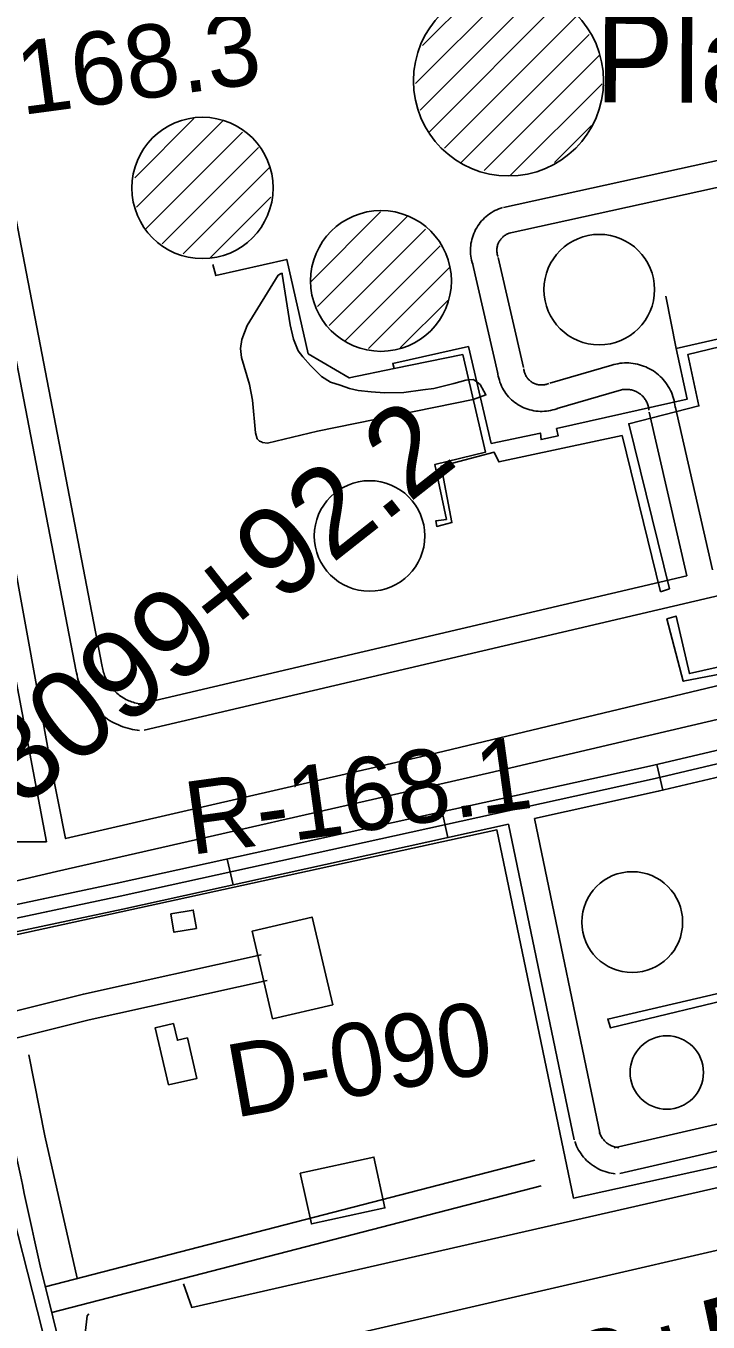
# Model space of a CAD drawing. Extents: x 3392644 to 3430565, y 576657 to 602123.
# Drawn here: x 3414906 to 3415681, y 584566 to 586038 of the extents above; entities that cross this region are included whole.
import ezdxf

# ---------------------------------------------------------------- set-up
doc = ezdxf.new("R2010")
doc.units = 0
for name, color, linetype in [('V-BLDG-IDEN', 7, 'Continuous'), ('V-BLDG-OTLN', 7, 'Continuous'), ('V-DOMW-TANK', 7, 'Continuous'), ('V-RIVR-RANG-IDEN', 7, 'Continuous'), ('V-ROAD-CNTR', 7, 'Continuous'), ('V-SITE-OTLN', 7, 'Continuous'), ('V-SURV-IDEN', 7, 'Continuous'), ('V-TOPO-SHOR', 7, 'Continuous'), ('V-UTIL-LINE', 7, 'Continuous')]:
    doc.layers.add(name, color=color, linetype=linetype)

msp = doc.modelspace()

# ---------------------------------------------------------------- linework, layer by layer
at = {"layer": 'V-BLDG-OTLN'}
for points in [[(3415070.6, 585029.5), (3415096.1, 585033.8), (3415099.6, 585013), (3415074.1, 585008.7)], [(3415186.3, 584910.3), (3415162.9, 585009.8), (3415231.2, 585025.8), (3415254.6, 584926.3)], [(3415067.9, 584835.1), (3415052.8, 584900), (3415073.6, 584904.9), (3415078.1, 584885.9), (3415089.5, 584888.6), (3415100.2, 584842.6)], [(3415217.7, 584735.1), (3415301.3, 584753.3), (3415313.9, 584695.5), (3415230.3, 584677.3)]]:
    msp.add_lwpolyline(points, close=True, dxfattribs=at)
at = {"layer": 'V-DOMW-TANK'}
for p, q in [((3415348.7, 585972.7), (3415458.2, 586082.1)), ((3415353.8, 585942.4), (3415488.3, 586076.9)), ((3415356.5, 586015.8), (3415415.2, 586074.5)), ((3415364.5, 585917.7), (3415511.3, 586064.6)), ((3415381.5, 585899.3), (3415532.2, 586050.1)), ((3415400.2, 585882.7), (3415545.8, 586028.3)), ((3415426.7, 585873.9), (3415557.4, 586004.5)), ((3415456.7, 585868.6), (3415560.7, 585972.5)), ((3415029.6, 585865.7), (3415096.9, 585932.9)), ((3415031.7, 585832.4), (3415129.6, 585930.3)), ((3415041.9, 585807.3), (3415152, 585917.4)), ((3415506.5, 585883), (3415548.5, 585924.9)), ((3415060.8, 585790.8), (3415170.2, 585900.2)), ((3415084.7, 585779.3), (3415182.5, 585877.1)), ((3415115.7, 585775), (3415184.2, 585843.5)), ((3415229.9, 585747.7), (3415309, 585826.9)), ((3415237.1, 585719.6), (3415339.8, 585822.3)), ((3415250.5, 585697.7), (3415360.1, 585807.3)), ((3415268.3, 585680.1), (3415376.5, 585788.3)), ((3415295.4, 585671.9), (3415387.4, 585763.8)), ((3415331.3, 585672.4), (3415385.3, 585726.4))]:
    msp.add_line(p, q, dxfattribs=at)
for centre, radius in [((3415454.3, 585975.7), 108), ((3415106.6, 585854.1), 80.3), ((3415309.4, 585748.5), 80), ((3415557.4, 585738.6), 62.8), ((3415296.4, 585458.8), 62.8), ((3415594.9, 585020.1), 57.3), ((3415634.2, 584849.3), 41.7)]:
    msp.add_circle(centre, radius, dxfattribs=at)
at = {"layer": 'V-ROAD-CNTR'}
for p, q in [((3415622.9, 585199.1), (3415629.8, 585169.9)), ((3415379, 585145.4), (3415385.4, 585116.1)), ((3415134.8, 585091.7), (3415141.3, 585062.4))]:
    msp.add_line(p, q, dxfattribs=at)
for points in [[(3414963.1, 585305), (3414684.5, 586747.9)], [(3414992.6, 585310.6), (3414810.3, 586254.8)], [(3415448.7, 585832.1), (3415983.1, 585949.3)], [(3415455.2, 585802.8), (3415989.5, 585920)], [(3415447.5, 585831.8), (3415445.5, 585831.2), (3415443.3, 585830.3), (3415441, 585829.4), (3415438.9, 585828.4), (3415436.8, 585827.2), (3415434.7, 585826), (3415432.7, 585824.7), (3415430.8, 585823.2), (3415428.9, 585821.7), (3415427.1, 585820.1), (3415425.4, 585818.4), (3415423.8, 585816.7), (3415422.2, 585814.8), (3415420.8, 585812.9), (3415419.4, 585811), (3415418.2, 585808.9), (3415417, 585806.8), (3415415.9, 585804.7), (3415414.9, 585802.5), (3415414.1, 585800.2), (3415413.3, 585798), (3415412.7, 585795.6), (3415412.1, 585793.3), (3415411.7, 585790.9), (3415411.4, 585788.6), (3415411.2, 585786.2), (3415411.1, 585783.8), (3415411.1, 585781.4), (3415411.3, 585779), (3415411.5, 585776.6), (3415411.9, 585774.2), (3415412.4, 585771.9), (3415413, 585769.5), (3415413.6, 585767.4), (3415413.7, 585767.1)], [(3415456.4, 585803.1), (3415455.2, 585802.7), (3415454.2, 585802.4), (3415453.3, 585802), (3415452.5, 585801.6), (3415451.6, 585801.1), (3415450.8, 585800.6), (3415449.9, 585800.1), (3415449.1, 585799.5), (3415448.4, 585798.9), (3415447.7, 585798.2), (3415447, 585797.5), (3415446.3, 585796.8), (3415445.7, 585796.1), (3415445.1, 585795.3), (3415444.5, 585794.5), (3415444, 585793.7), (3415443.5, 585792.8), (3415443.1, 585791.9), (3415442.7, 585791), (3415442.3, 585790.1), (3415442, 585789.2), (3415441.8, 585788.2), (3415441.5, 585787.3), (3415441.4, 585786.3), (3415441.2, 585785.3), (3415441.2, 585784.4), (3415441.1, 585783.4), (3415441.1, 585782.4), (3415441.2, 585781.4), (3415441.3, 585780.5), (3415441.4, 585779.5), (3415441.6, 585778.5), (3415441.9, 585777.6), (3415442.2, 585776.5), (3415442.2, 585776.6)], [(3417410.7, 585793.4), (3415040.3, 585238.2)], [(3415413.3, 585768.5), (3415442.2, 585643.3)], [(3415442.5, 585775.2), (3415471.4, 585650)], [(3415471.7, 585648.7), (3415471.9, 585647.4), (3415472, 585646.4), (3415472.2, 585645.5), (3415472.5, 585644.5), (3415472.8, 585643.6), (3415473.2, 585642.7), (3415473.6, 585641.9), (3415474, 585641), (3415474.5, 585640.1), (3415475, 585639.3), (3415475.5, 585638.5), (3415476.1, 585637.8), (3415476.8, 585637), (3415477.4, 585636.3), (3415478.1, 585635.7), (3415478.8, 585635), (3415479.6, 585634.4), (3415480.4, 585633.8), (3415481.2, 585633.3), (3415482, 585632.8), (3415482.9, 585632.4), (3415483.8, 585632), (3415484.6, 585631.6), (3415485.6, 585631.3), (3415486.5, 585631), (3415487.4, 585630.8), (3415488.4, 585630.6), (3415489.3, 585630.4), (3415490.3, 585630.3), (3415491.2, 585630.3), (3415492.2, 585630.3), (3415493.2, 585630.3), (3415494.1, 585630.4), (3415495.1, 585630.5), (3415496.1, 585630.7), (3415497, 585630.9), (3415497.9, 585631.2), (3415498.9, 585631.5), (3415500, 585631.9)], [(3415501.3, 585632.4), (3415571.8, 585652.9)], [(3415571.8, 585652.9), (3415573.9, 585653.5), (3415576.3, 585654), (3415578.7, 585654.5), (3415581.2, 585654.9), (3415583.6, 585655.1), (3415586.1, 585655.3), (3415588.5, 585655.3), (3415591, 585655.3), (3415593.5, 585655.1), (3415595.9, 585654.8), (3415598.4, 585654.4), (3415600.8, 585653.9), (3415603.2, 585653.3), (3415605.6, 585652.6), (3415607.9, 585651.8), (3415610.2, 585650.8), (3415612.4, 585649.8), (3415614.6, 585648.7), (3415616.8, 585647.5), (3415618.9, 585646.2), (3415620.9, 585644.8), (3415622.9, 585643.3), (3415624.8, 585641.7), (3415626.6, 585640), (3415628.4, 585638.3), (3415630.1, 585636.5), (3415631.7, 585634.6), (3415633.2, 585632.7), (3415634.6, 585630.6), (3415635.9, 585628.6), (3415637.2, 585626.4), (3415638.3, 585624.2), (3415639.4, 585622), (3415640.3, 585619.7), (3415641.1, 585617.4), (3415641.9, 585615), (3415642.5, 585612.6), (3415643, 585610.2), (3415643.5, 585607.8), (3415643.8, 585605.4), (3415643.9, 585604.3)], [(3415441.9, 585644.7), (3415442.2, 585642.6), (3415442.7, 585640.3), (3415443.2, 585638), (3415443.9, 585635.7), (3415444.6, 585633.4), (3415445.5, 585631.2), (3415446.5, 585629), (3415447.5, 585626.8), (3415448.7, 585624.7), (3415450, 585622.7), (3415451.4, 585620.8), (3415452.8, 585618.9), (3415454.4, 585617), (3415456, 585615.3), (3415457.7, 585613.6), (3415459.5, 585612), (3415461.4, 585610.5), (3415463.4, 585609.1), (3415465.4, 585607.8), (3415467.4, 585606.6), (3415469.5, 585605.5), (3415471.7, 585604.5), (3415473.9, 585603.6), (3415476.2, 585602.8), (3415478.5, 585602.1), (3415480.8, 585601.5), (3415483.1, 585601), (3415485.5, 585600.7), (3415487.9, 585600.4), (3415490.3, 585600.3), (3415492.7, 585600.3), (3415495.1, 585600.4), (3415497.5, 585600.6), (3415499.8, 585600.9), (3415502.2, 585601.3), (3415504.5, 585601.9), (3415506.8, 585602.5), (3415509.1, 585603.3), (3415510.9, 585604)], [(3415509.6, 585603.6), (3415580.2, 585624.1)], [(3415580.2, 585624.1), (3415581.6, 585624.5), (3415582.7, 585624.7), (3415583.8, 585625), (3415585, 585625.1), (3415586.1, 585625.2), (3415587.2, 585625.3), (3415588.4, 585625.3), (3415589.5, 585625.3), (3415590.7, 585625.2), (3415591.8, 585625.1), (3415592.9, 585624.9), (3415594, 585624.7), (3415595.2, 585624.4), (3415596.3, 585624.1), (3415597.3, 585623.7), (3415598.4, 585623.3), (3415599.4, 585622.8), (3415600.5, 585622.3), (3415601.4, 585621.7), (3415602.4, 585621.1), (3415603.4, 585620.4), (3415604.3, 585619.8), (3415605.2, 585619), (3415606, 585618.3), (3415606.8, 585617.5), (3415607.6, 585616.6), (3415608.3, 585615.7), (3415609, 585614.8), (3415609.7, 585613.9), (3415610.3, 585612.9), (3415610.9, 585612), (3415611.4, 585610.9), (3415611.9, 585609.9), (3415612.3, 585608.8), (3415612.7, 585607.8), (3415613.1, 585606.7), (3415613.4, 585605.6), (3415613.6, 585604.4), (3415613.8, 585603.3), (3415613.9, 585602.1), (3415614, 585601.5)], [(3415643.6, 585606.2), (3415686.3, 585420.3)], [(3415614.3, 585599.5), (3415657.1, 585413.5)], [(3415657.1, 585413.5), (3415033.4, 585267.4)], [(3415038.5, 585267.7), (3415036.5, 585267.9), (3415034.7, 585268.2), (3415033, 585268.5), (3415031.2, 585268.9), (3415029.5, 585269.3), (3415027.8, 585269.8), (3415026.1, 585270.4), (3415024.5, 585271), (3415022.8, 585271.6), (3415021.2, 585272.4), (3415019.6, 585273.2), (3415018, 585274), (3415016.5, 585274.9), (3415015, 585275.9), (3415013.5, 585276.8), (3415012.1, 585277.9), (3415010.7, 585279), (3415009.4, 585280.2), (3415008, 585281.3), (3415006.8, 585282.6), (3415005.5, 585283.9), (3415004.3, 585285.2), (3415003.2, 585286.6), (3415002.1, 585288), (3415001.1, 585289.4), (3415000.1, 585290.9), (3414999.2, 585292.4), (3414998.3, 585293.9), (3414997.4, 585295.5), (3414996.7, 585297.1), (3414996, 585298.7), (3414995.3, 585300.4), (3414994.7, 585302), (3414994.1, 585303.7), (3414993.7, 585305.4), (3414993.2, 585307.2), (3414992.9, 585308.9), (3414992.6, 585310.4)], [(3415035.2, 585237.9), (3415032.7, 585238.1), (3415029.9, 585238.6), (3415027.1, 585239.1), (3415024.3, 585239.7), (3415021.6, 585240.4), (3415018.9, 585241.2), (3415016.2, 585242), (3415013.6, 585243), (3415011, 585244.1), (3415008.4, 585245.2), (3415005.9, 585246.5), (3415003.4, 585247.8), (3415000.9, 585249.3), (3414998.5, 585250.8), (3414996.2, 585252.4), (3414993.9, 585254), (3414991.7, 585255.8), (3414989.6, 585257.6), (3414987.5, 585259.5), (3414985.5, 585261.4), (3414983.5, 585263.5), (3414981.6, 585265.6), (3414979.8, 585267.8), (3414978.1, 585270), (3414976.4, 585272.3), (3414974.9, 585274.6), (3414973.4, 585277), (3414972, 585279.5), (3414970.7, 585282), (3414969.4, 585284.5), (3414968.3, 585287.1), (3414967.3, 585289.7), (3414966.3, 585292.3), (3414965.4, 585295), (3414964.7, 585297.7), (3414964, 585300.5), (3414963.4, 585303.2), (3414963.1, 585305.2)], [(3414841.6, 585028.8), (3415009.8, 585064.2), (3415617.8, 585197.9), (3415939.4, 585273.8)], [(3415942.8, 585259.2), (3415621.1, 585183.3), (3415013, 585049.5), (3414844.7, 585014.1)], [(3415483.8, 585137.7), (3415624.5, 585168.7), (3415856.2, 585223.3)], [(3415558.3, 584779), (3415483.8, 585137.7)], [(3414847.8, 584999.4), (3415016.2, 585034.9), (3415454.5, 585131.3)], [(3415528.9, 584772.9), (3415454.5, 585131.3)], [(3414862.6, 584911.3), (3414971.2, 584938.4), (3415173.4, 584983.1)], [(3414869.8, 584882.2), (3414978, 584909.2), (3415179.9, 584953.8)], [(3416061.2, 584875.8), (3415574.2, 584763.6)], [(3416068, 584846.6), (3415580.9, 584734.4)], [(3415579.5, 584763.9), (3415578, 584764.1), (3415576.9, 584764.3), (3415575.8, 584764.5), (3415574.7, 584764.8), (3415573.6, 584765.1), (3415572.6, 584765.5), (3415571.5, 584766), (3415570.5, 584766.4), (3415569.5, 584767), (3415568.5, 584767.5), (3415567.6, 584768.2), (3415566.7, 584768.8), (3415565.8, 584769.5), (3415564.9, 584770.2), (3415564.1, 584771), (3415563.3, 584771.8), (3415562.5, 584772.7), (3415561.8, 584773.5), (3415561.1, 584774.4), (3415560.5, 584775.4), (3415559.9, 584776.3), (3415559.4, 584777.3), (3415558.9, 584778.3), (3415558.4, 584779.4), (3415557.9, 584780.5), (3415557.8, 584781)], [(3415575.6, 584734.1), (3415573.5, 584734.4), (3415571.1, 584734.8), (3415568.7, 584735.4), (3415566.3, 584736), (3415564, 584736.7), (3415561.6, 584737.6), (3415559.4, 584738.5), (3415557.1, 584739.6), (3415555, 584740.7), (3415552.8, 584742), (3415550.8, 584743.3), (3415548.7, 584744.7), (3415546.8, 584746.3), (3415544.9, 584747.9), (3415543.1, 584749.5), (3415541.4, 584751.3), (3415539.7, 584753.1), (3415538.2, 584755), (3415536.7, 584757), (3415535.3, 584759.1), (3415534, 584761.2), (3415532.8, 584763.3), (3415531.7, 584765.5), (3415530.7, 584767.8), (3415529.9, 584770), (3415529.5, 584770.9)], [(3414927.8, 584605.8), (3415484.1, 584749.6)], [(3414935.3, 584576.8), (3415491.6, 584720.5)], [(3414922, 584629.6), (3415169.2, 583635.6)]]:
    msp.add_lwpolyline(points, dxfattribs=at)
msp.add_arc((3426787.9, 587247.6), 12151.3, 190.8528, 192.44192, dxfattribs=at)
at = {"layer": 'V-SITE-OTLN'}
msp.add_lwpolyline([(3416164.3, 584550.7), (3416161.1, 584568), (3416097, 584831.4), (3415528, 584706.7), (3415441.1, 585124.8), (3414885.8, 585003.9), (3414787.6, 585534.1), (3414674, 586142.1), (3414579.1, 586564.1), (3414488.4, 587013.5), (3414833, 587097.6), (3414846.4, 587100.5), (3414856, 587102.4), (3414865.5, 587103.9), (3415026.6, 587138), (3415544.3, 587252.4), (3415572.5, 587260.1), (3415594.5, 587264.5), (3415667.1, 587280.6), (3416201.5, 587400.8), (3417016.1, 587577.2)], dxfattribs=at)
at = {"layer": 'V-TOPO-SHOR'}
for points in [[(3415414.3, 585613.9), (3415237.3, 585577.9), (3415180.4, 585564.1), (3415174.9, 585564.9), (3415173.6, 585565.6), (3415171.5, 585566.3), (3415168.8, 585569.1), (3415166.9, 585575.9), (3415163.6, 585612.9), (3415159.9, 585630.7), (3415151, 585661.6), (3415149.8, 585671.9), (3415151.4, 585682.1), (3415157.2, 585697.7), (3415192.5, 585755), (3415196, 585757), (3415197.3, 585757), (3415197.3, 585756.3), (3415206.4, 585698.7), (3415210.1, 585682.3), (3415215.3, 585669.2), (3415220.6, 585662.3), (3415229.3, 585652.5), (3415242, 585640), (3415252.1, 585633.6), (3415263, 585630), (3415273.8, 585626.3), (3415283.4, 585624.1), (3415298.3, 585622.4), (3415313.4, 585621.4), (3415335.2, 585621.6), (3415357.1, 585624.6), (3415369.5, 585626.4), (3415392.1, 585632.1), (3415405.9, 585635.9), (3415414.1, 585636.4), (3415416.8, 585635), (3415422.1, 585630.8), (3415426.1, 585623.2), (3415428.7, 585619), (3415414.3, 585613.9)], [(3414964, 584615.6), (3414927.5, 584777.2), (3414909.2, 584869.2)], [(3415085.2, 584609.3), (3415094.3, 584582.4), (3416106.1, 584812.9), (3416122.1, 584745.6), (3416077.2, 584736.4), (3415168.6, 584526.6), (3415139.4, 584535.4), (3414977.9, 584496.7), (3414971, 584532.6), (3414973.2, 584552.8), (3414975.4, 584573), (3414977.6, 584575.3)], [(3414880.2, 584731.1), (3414924.4, 584556.8), (3414972.2, 584359.3), (3414995.6, 584271.5), (3415033.2, 584110.3), (3415034.6, 584109.6), (3415036.6, 584109.6)]]:
    msp.add_lwpolyline(points, dxfattribs=at)
at = {"layer": 'V-UTIL-LINE'}
for p, q in [((3415644.7, 585671.7), (3415633.2, 585731.2)), ((3415637.2, 585398.6), (3415627.1, 585395.2))]:
    msp.add_line(p, q, dxfattribs=at)
for points in [[(3414748.9, 586207.2), (3414831.3, 585765), (3414934.3, 585199.3), (3414951, 585115), (3415354.5, 585207.7), (3415760.9, 585305.2), (3415759.7, 585314.1), (3415652.8, 585293.8), (3415634.4, 585364.5), (3415644.7, 585367.7), (3415659.8, 585302.5), (3415735.9, 585319.4), (3415731.5, 585341.4), (3416082.4, 585422.3), (3416225.2, 585455.5)], [(3415324.5, 585649.2), (3415273.3, 585638.4), (3415226.5, 585665.8), (3415202.3, 585772.9), (3415121.7, 585754.5), (3415118.4, 585767.3)], [(3415627.1, 585395.2), (3415583.4, 585572.8), (3415443.4, 585542.9), (3415438.2, 585553.9), (3415377.8, 585537.9), (3415390.1, 585473.9), (3415372.7, 585469.7), (3415371.9, 585476.1), (3415383.8, 585477.6), (3415370.5, 585539.8), (3415428.2, 585554.1), (3415402.3, 585664.9), (3415324.5, 585649.2), (3415322.8, 585654.7), (3415408.8, 585673.9), (3415434.8, 585564), (3415490.6, 585575.6), (3415491.3, 585568.3), (3415510.6, 585572.5), (3415508.9, 585580.7), (3415657.2, 585614.1), (3415644.7, 585671.7), (3415766.4, 585699.3)], [(3415769, 585691.9), (3415658.2, 585665.1), (3415670.7, 585606.5), (3415591, 585586.3), (3415637.2, 585398.6)], [(3416238, 585378.8), (3415977.9, 585319.3), (3415876.3, 585296.8), (3415874.4, 585303.7), (3415862.1, 585301.2), (3415864.5, 585288.8), (3415728.7, 585258.9), (3415432.9, 585189.8), (3414940.8, 585077.8), (3414887.3, 585065.2)], [(3414875.9, 585111.2), (3414929.2, 585111.5), (3414894.1, 585298)], [(3415822.5, 585279.6), (3415829.1, 585252.5), (3415830.9, 585251.6), (3415841.7, 585202.2), (3415842.5, 585195.8), (3415890.8, 584977.1), (3415570.4, 584899.9), (3415567, 584910), (3415880.9, 584982.8), (3415833.4, 585195.1), (3415830.8, 585199.7), (3415820.7, 585242.7), (3415819.9, 585249.1), (3415813.4, 585277.6), (3415822.5, 585279.6)]]:
    msp.add_lwpolyline(points, dxfattribs=at)

# ---------------------------------------------------------------- texts
at = {"layer": 'V-BLDG-IDEN'}
msp.add_text('Plantation', height=100, rotation=359.6858, dxfattribs=at).set_placement((3415552.7, 585951.6))
at = {"layer": 'V-RIVR-RANG-IDEN'}
for s, rotation, p in [('R-168.3', 7.624, (3414785.1, 585921.3)), ('R-168.1', 7.8765, (3415093.1, 585096.3)), ('D-090', 9.9991, (3415143.2, 584797.7))]:
    msp.add_text(s, height=83, rotation=rotation, dxfattribs=at).set_placement(p)
at = {"layer": 'V-SURV-IDEN'}
for s, rotation, p in [('3099+92.2', 38.2304, (3414900, 585148.1)), ('3108+53.2', 15.2822, (3415329.3, 584391.4))]:
    msp.add_text(s, height=100, rotation=rotation, dxfattribs=at).set_placement(p)

doc.saveas('drawing.dxf')
